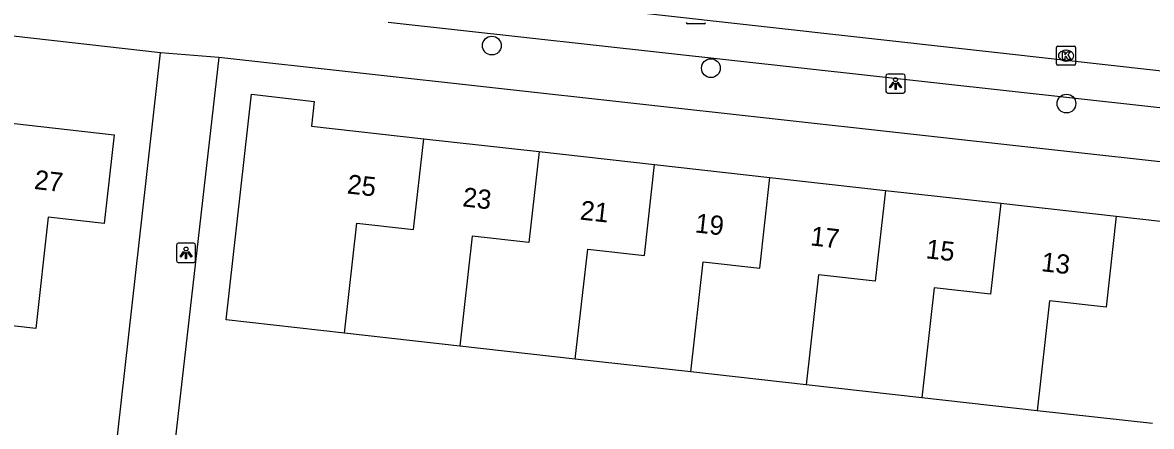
# Model space of a CAD drawing. Extents: x 162082 to 163393, y 388091 to 388632.
# Drawn here: x 162786.3 to 162845.1, y 388315.9 to 388337 of the extents above; entities that cross this region are included whole.
import ezdxf

# ---------------------------------------------------------------- set-up
doc = ezdxf.new("R2010")
doc.units = 0
for name, color, linetype in [('IMGEO_Boom', 7, 'Continuous'), ('IMGEO_Kolk', 7, 'Continuous'), ('IMGEO_Lichtpunt', 7, 'Continuous'), ('IMGEO_Pand', 7, 'Continuous'), ('IMGEO_Pand_nummerreeks', 7, 'Continuous'), ('IMGEO_Rijbaan_lokaal_open', 7, 'Continuous'), ('IMGEO_Voetpad_open', 7, 'Continuous')]:
    doc.layers.add(name, color=color, linetype=linetype)

msp = doc.modelspace()

# ---------------------------------------------------------------- linework, layer by layer
at = {"layer": 'IMGEO_Boom'}
for centre in [(162810.716, 388335.763), (162822.134, 388334.587), (162840.665, 388332.74)]:
    msp.add_circle(centre, 0.489, dxfattribs=at)
at = {"layer": 'IMGEO_Kolk'}
for p, q in [((162821.776, 388336.889), (162820.924, 388336.889)), ((162840.143, 388334.811), (162840.143, 388335.663)), ((162840.218, 388335.737), (162841.07, 388335.737)), ((162840.631, 388335.517), (162840.656, 388335.517)), ((162841.144, 388335.663), (162841.144, 388334.811)), ((162841.07, 388334.737), (162840.218, 388334.737)), ((162840.654, 388334.957), (162840.629, 388334.957))]:
    msp.add_line(p, q, dxfattribs=at)
for points in [[(162821.776, 388336.889), (162820.924, 388336.889)], [(162840.143, 388334.811), (162840.143, 388335.663)], [(162840.218, 388335.737), (162841.07, 388335.737)], [(162840.464, 388335.437), (162840.587, 388335.437), (162840.587, 388335.286), (162840.717, 388335.437), (162840.881, 388335.437), (162840.735, 388335.286), (162840.888, 388335.037), (162840.736, 388335.037), (162840.651, 388335.201), (162840.587, 388335.134), (162840.587, 388335.037), (162840.464, 388335.037), (162840.464, 388335.437)], [(162841.144, 388335.663), (162841.144, 388334.811)], [(162841.07, 388334.737), (162840.218, 388334.737)]]:
    msp.add_lwpolyline(points, dxfattribs=at)
for centre, start, end in [((162820.926, 388336.965), 181.55205, 268.44795), ((162820.926, 388336.965), 181.55205, 268.44795), ((162821.774, 388336.965), 271.55205, 358.44795), ((162821.774, 388336.965), 271.55205, 358.44795), ((162840.22, 388335.661), 91.55205, 178.44795), ((162840.22, 388335.661), 91.55205, 178.44795), ((162841.068, 388335.661), 1.55205, 88.44795), ((162841.068, 388335.661), 1.55205, 88.44795), ((162840.22, 388334.813), 181.55205, 268.44795), ((162840.22, 388334.813), 181.55205, 268.44795), ((162841.068, 388334.813), 271.55205, 358.44795), ((162841.068, 388334.813), 271.55205, 358.44795)]:
    msp.add_arc(centre, 0.0765, start, end, dxfattribs=at)
for centre, major_axis, ratio, start_param, end_param in [((162840.63, 388335.237), (-0.387, 0.002), 0.722429, 4.712389, 7.853982), ((162840.655, 388335.237), (-0.39, 0.002), 0.717154, 1.570796, 4.712389)]:
    msp.add_ellipse(centre, major_axis=major_axis, ratio=ratio, start_param=start_param, end_param=end_param, dxfattribs=at)
at = {"layer": 'IMGEO_Lichtpunt'}
for p, q in [((162831.259, 388334.185), (162831.259, 388333.378)), ((162831.259, 388334.185), (162831.259, 388333.378)), ((162832.161, 388334.28), (162831.353, 388334.28)), ((162832.161, 388334.28), (162831.353, 388334.28)), ((162832.255, 388333.378), (162832.255, 388334.185)), ((162832.255, 388333.378), (162832.255, 388334.185)), ((162831.353, 388333.284), (162832.161, 388333.284)), ((162831.353, 388333.284), (162832.161, 388333.284)), ((162794.281, 388325.36), (162794.281, 388324.553)), ((162794.281, 388325.36), (162794.281, 388324.553)), ((162795.183, 388325.455), (162794.375, 388325.455)), ((162795.183, 388325.455), (162794.375, 388325.455)), ((162795.277, 388324.553), (162795.277, 388325.36)), ((162795.277, 388324.553), (162795.277, 388325.36)), ((162794.375, 388324.459), (162795.183, 388324.459)), ((162794.375, 388324.459), (162795.183, 388324.459))]:
    msp.add_line(p, q, dxfattribs=at)
for points in [[(162831.633, 388333.849), (162831.672, 388333.821), (162831.484, 388333.559), (162831.446, 388333.586), (162831.633, 388333.849)], [(162831.735, 388333.801), (162831.782, 388333.801), (162831.782, 388333.479), (162831.735, 388333.479), (162831.735, 388333.801)], [(162831.845, 388333.821), (162831.883, 388333.848), (162832.07, 388333.586), (162832.031, 388333.558), (162831.845, 388333.821)], [(162794.655, 388325.024), (162794.694, 388324.996), (162794.506, 388324.734), (162794.468, 388324.761), (162794.655, 388325.024)], [(162794.757, 388324.976), (162794.804, 388324.976), (162794.804, 388324.654), (162794.757, 388324.654), (162794.757, 388324.976)], [(162794.867, 388324.996), (162794.905, 388325.023), (162795.092, 388324.761), (162795.053, 388324.733), (162794.867, 388324.996)]]:
    msp.add_lwpolyline(points, dxfattribs=at)
for centre in [(162831.758, 388333.983), (162794.78, 388325.158)]:
    msp.add_circle(centre, 0.0994, dxfattribs=at)
for centre, start, end in [((162831.353, 388334.185), 90, 180), ((162831.353, 388334.185), 90, 180), ((162832.161, 388334.185), 0, 90), ((162832.161, 388334.185), 0, 90), ((162831.353, 388333.378), 180, 270), ((162831.353, 388333.378), 180, 270), ((162832.161, 388333.378), 270, 0), ((162832.161, 388333.378), 270, 360), ((162794.375, 388325.36), 90, 180), ((162794.375, 388325.36), 90, 180), ((162795.183, 388325.36), 0, 90), ((162795.183, 388325.36), 0, 90), ((162794.375, 388324.553), 180, 270), ((162794.375, 388324.553), 180, 270), ((162795.183, 388324.553), 270, 0), ((162795.183, 388324.553), 270, 360)]:
    msp.add_arc(centre, 0.0946, start, end, dxfattribs=at)
at = {"layer": 'IMGEO_Pand'}
for points in [[(162803.032, 388320.771), (162796.87, 388321.461), (162798.186, 388333.222), (162801.466, 388332.855), (162801.322, 388331.563), (162807.167, 388330.908)], [(162784.893, 388331.813), (162791.04, 388331.116), (162790.515, 388326.482), (162787.602, 388326.812), (162786.944, 388321.006), (162780.783, 388321.705)], [(162803.032, 388320.771), (162803.677, 388326.504), (162806.637, 388326.173), (162807.167, 388330.908)], [(162807.167, 388330.908), (162813.182, 388330.235)], [(162813.182, 388330.235), (162812.651, 388325.499), (162809.695, 388325.83), (162809.05, 388320.097)], [(162813.182, 388330.235), (162819.197, 388329.561)], [(162815.067, 388319.423), (162815.712, 388325.156), (162818.666, 388324.825), (162819.197, 388329.561)], [(162819.197, 388329.561), (162825.213, 388328.887)], [(162821.085, 388318.749), (162821.73, 388324.482), (162824.682, 388324.151), (162825.213, 388328.887)], [(162825.213, 388328.887), (162831.228, 388328.213)], [(162831.228, 388328.213), (162830.697, 388323.477), (162827.747, 388323.807), (162827.102, 388318.076)], [(162831.228, 388328.213), (162837.243, 388327.54)], [(162837.243, 388327.54), (162836.712, 388322.803), (162833.764, 388323.133), (162833.119, 388317.402)], [(162837.243, 388327.54), (162843.259, 388326.866)], [(162843.259, 388326.866), (162842.728, 388322.129), (162839.781, 388322.459), (162839.137, 388316.728)], [(162843.259, 388326.866), (162849.274, 388326.192)], [(162809.05, 388320.097), (162803.032, 388320.771)], [(162815.067, 388319.423), (162809.05, 388320.097)], [(162821.085, 388318.749), (162815.067, 388319.423)], [(162827.102, 388318.076), (162821.085, 388318.749)], [(162833.119, 388317.402), (162827.102, 388318.076)], [(162839.137, 388316.728), (162833.119, 388317.402)], [(162845.154, 388316.054), (162839.137, 388316.728)]]:
    msp.add_lwpolyline(points, dxfattribs=at)
at = {"layer": 'IMGEO_Rijbaan_lokaal_open'}
msp.add_lwpolyline([(162802.146, 388339.314), (162880.401, 388330.569)], dxfattribs=at)
at = {"layer": 'IMGEO_Voetpad_open'}
for points in [[(162793.443, 388335.388), (162740.3, 388341.413)], [(162876.952, 388329.043), (162805.311, 388336.967)], [(162790.857, 388312.329), (162793.443, 388335.388)], [(162796.49, 388335.147), (162793.443, 388335.388)], [(162796.49, 388335.147), (162793.989, 388313.237)], [(162882.015, 388325.663), (162868.576, 388327.156), (162796.49, 388335.147)]]:
    msp.add_lwpolyline(points, dxfattribs=at)

# ---------------------------------------------------------------- texts
at = {"layer": 'IMGEO_Pand_nummerreeks'}
for s, rotation, p in [('27', 353.53146, (162786.831, 388328.292)), ('25', 353.60937, (162803.143, 388328.059)), ('23', 353.60937, (162809.157, 388327.386)), ('21', 353.60937, (162815.282, 388326.699)), ('19', 353.60937, (162821.274, 388326.028)), ('17', 353.60937, (162827.287, 388325.354)), ('15', 353.60937, (162833.301, 388324.681)), ('13', 353.60937, (162839.315, 388324.007))]:
    msp.add_text(s, height=1, rotation=rotation, dxfattribs=at).set_placement(p)

doc.saveas('drawing.dxf')
